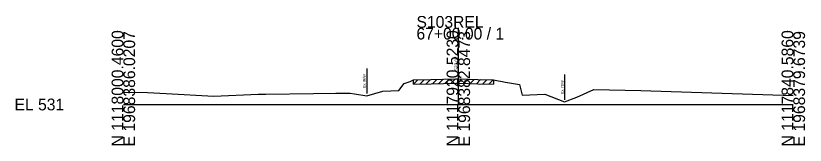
# Model space of a CAD drawing. Extents: x -26 to 163, y -10 to 24518.
# Drawn here: x -25.7 to 162.8, y 15490.3 to 15521.1 of the extents above; entities that cross this region are included whole.
import ezdxf

# ---------------------------------------------------------------- set-up
doc = ezdxf.new("R2010")
doc.units = 0
for name, color, linetype in [('RD_GPK_XS_Cell', 7, 'Continuous'), ('RD_XS_ExGround', 7, 'Continuous'), ('RD_XS_ExPaveRet', 7, 'Continuous'), ('RD_XS_ExRW', 7, 'Continuous'), ('RD_XS_TX_Elev_EX', 7, 'Continuous')]:
    doc.layers.add(name, color=color, linetype=linetype)

msp = doc.modelspace()

# ---------------------------------------------------------------- linework, layer by layer
at = {"layer": 'RD_GPK_XS_Cell'}
for p, q in [((80, 15500), (80, 15518.27)), ((0, 15500), (80, 15500)), ((80, 15500), (160, 15500))]:
    msp.add_line(p, q, dxfattribs=at)
at = {"layer": 'RD_XS_ExGround'}
msp.add_lwpolyline([(0, 15502.92), (5.74, 15502.84), (10.26, 15502.58), (21.6, 15501.96), (32.22, 15502.43), (32.92, 15502.46), (33.99, 15502.48), (45.43, 15502.62), (50.76, 15502.7), (54.16, 15502.66), (55.2, 15502.51), (58.12, 15502.09), (61.93, 15503.17), (65.82, 15503.34), (67.04, 15505.01), (68.46, 15505.46), (69.31, 15505.83), (73.48, 15505.93), (79.4, 15506.09), (80, 15506.07), (84.66, 15505.93), (88.39, 15505.83), (91.28, 15505.34), (94.63, 15504.74), (95.28, 15502.25), (100.62, 15502.42), (105.36, 15500.62), (108.32, 15501.73), (112.33, 15503.56), (123.62, 15503.36), (160, 15502.12)], dxfattribs=at)
at = {"layer": 'RD_XS_ExPaveRet'}
for p, q in [((69.31, 15504.83), (70.33, 15505.85)), ((69.31, 15504.83), (69.31, 15505.83)), ((69.31, 15504.83), (73.48, 15504.93)), ((70.81, 15504.86), (71.83, 15505.89)), ((72.31, 15504.9), (73.33, 15505.93)), ((73.48, 15504.93), (79.4, 15505.09)), ((73.81, 15504.94), (74.84, 15505.97)), ((75.31, 15504.98), (76.34, 15506.01)), ((76.81, 15505.02), (77.84, 15506.05)), ((78.31, 15505.06), (79.34, 15506.09)), ((79.4, 15505.09), (80, 15505.07)), ((79.81, 15505.08), (80.78, 15506.05)), ((80, 15505.07), (84.66, 15504.93)), ((81.31, 15505.03), (82.28, 15506)), ((82.81, 15504.99), (83.78, 15505.96)), ((84.31, 15504.94), (85.28, 15505.92)), ((84.66, 15504.93), (88.39, 15504.83)), ((85.81, 15504.9), (86.78, 15505.87)), ((87.31, 15504.86), (88.28, 15505.83)), ((88.39, 15505.83), (88.39, 15504.83))]:
    msp.add_line(p, q, dxfattribs=at)
at = {"layer": 'RD_XS_ExRW'}
for p, q in [((58.12, 15508.59), (58.12, 15502.59)), ((58.12, 15508.59), (58.12, 15502.59)), ((105.39, 15507.13), (105.39, 15501.13))]:
    msp.add_line(p, q, dxfattribs=at)

# ---------------------------------------------------------------- texts
at = {"layer": 'RD_GPK_XS_Cell'}
for s, p in [('S103REL', (70, 15518.27)), ('67+00.00 / 1', (70, 15515.47)), ('EL 531', (-26, 15498.6))]:
    msp.add_text(s, height=2.8, dxfattribs=at).set_placement(p)
for s, p in [('N 1118000.4600', (0, 15490)), ('E 1968386.0207', (2.8, 15490)), ('N 1117920.5230', (80, 15490)), ('E 1968382.8473', (82.8, 15490)), ('N 1117840.5860', (160, 15490)), ('E 1968379.6739', (162.8, 15490))]:
    msp.add_text(s, height=2.8, rotation=90, dxfattribs=at).set_placement(p)
at = {"layer": 'RD_XS_ExRW'}
for p in [(57.87, 15503.93), (57.87, 15503.93), (105.14, 15502.47)]:
    msp.add_text('Ex. R/W ', height=0.65, rotation=90, dxfattribs=at).set_placement(p)
at = {"layer": 'RD_XS_TX_Elev_EX'}
msp.add_text('537.07', height=0.8, rotation=90, dxfattribs=at).set_placement((79.9, 15508.07))

doc.saveas('drawing.dxf')
